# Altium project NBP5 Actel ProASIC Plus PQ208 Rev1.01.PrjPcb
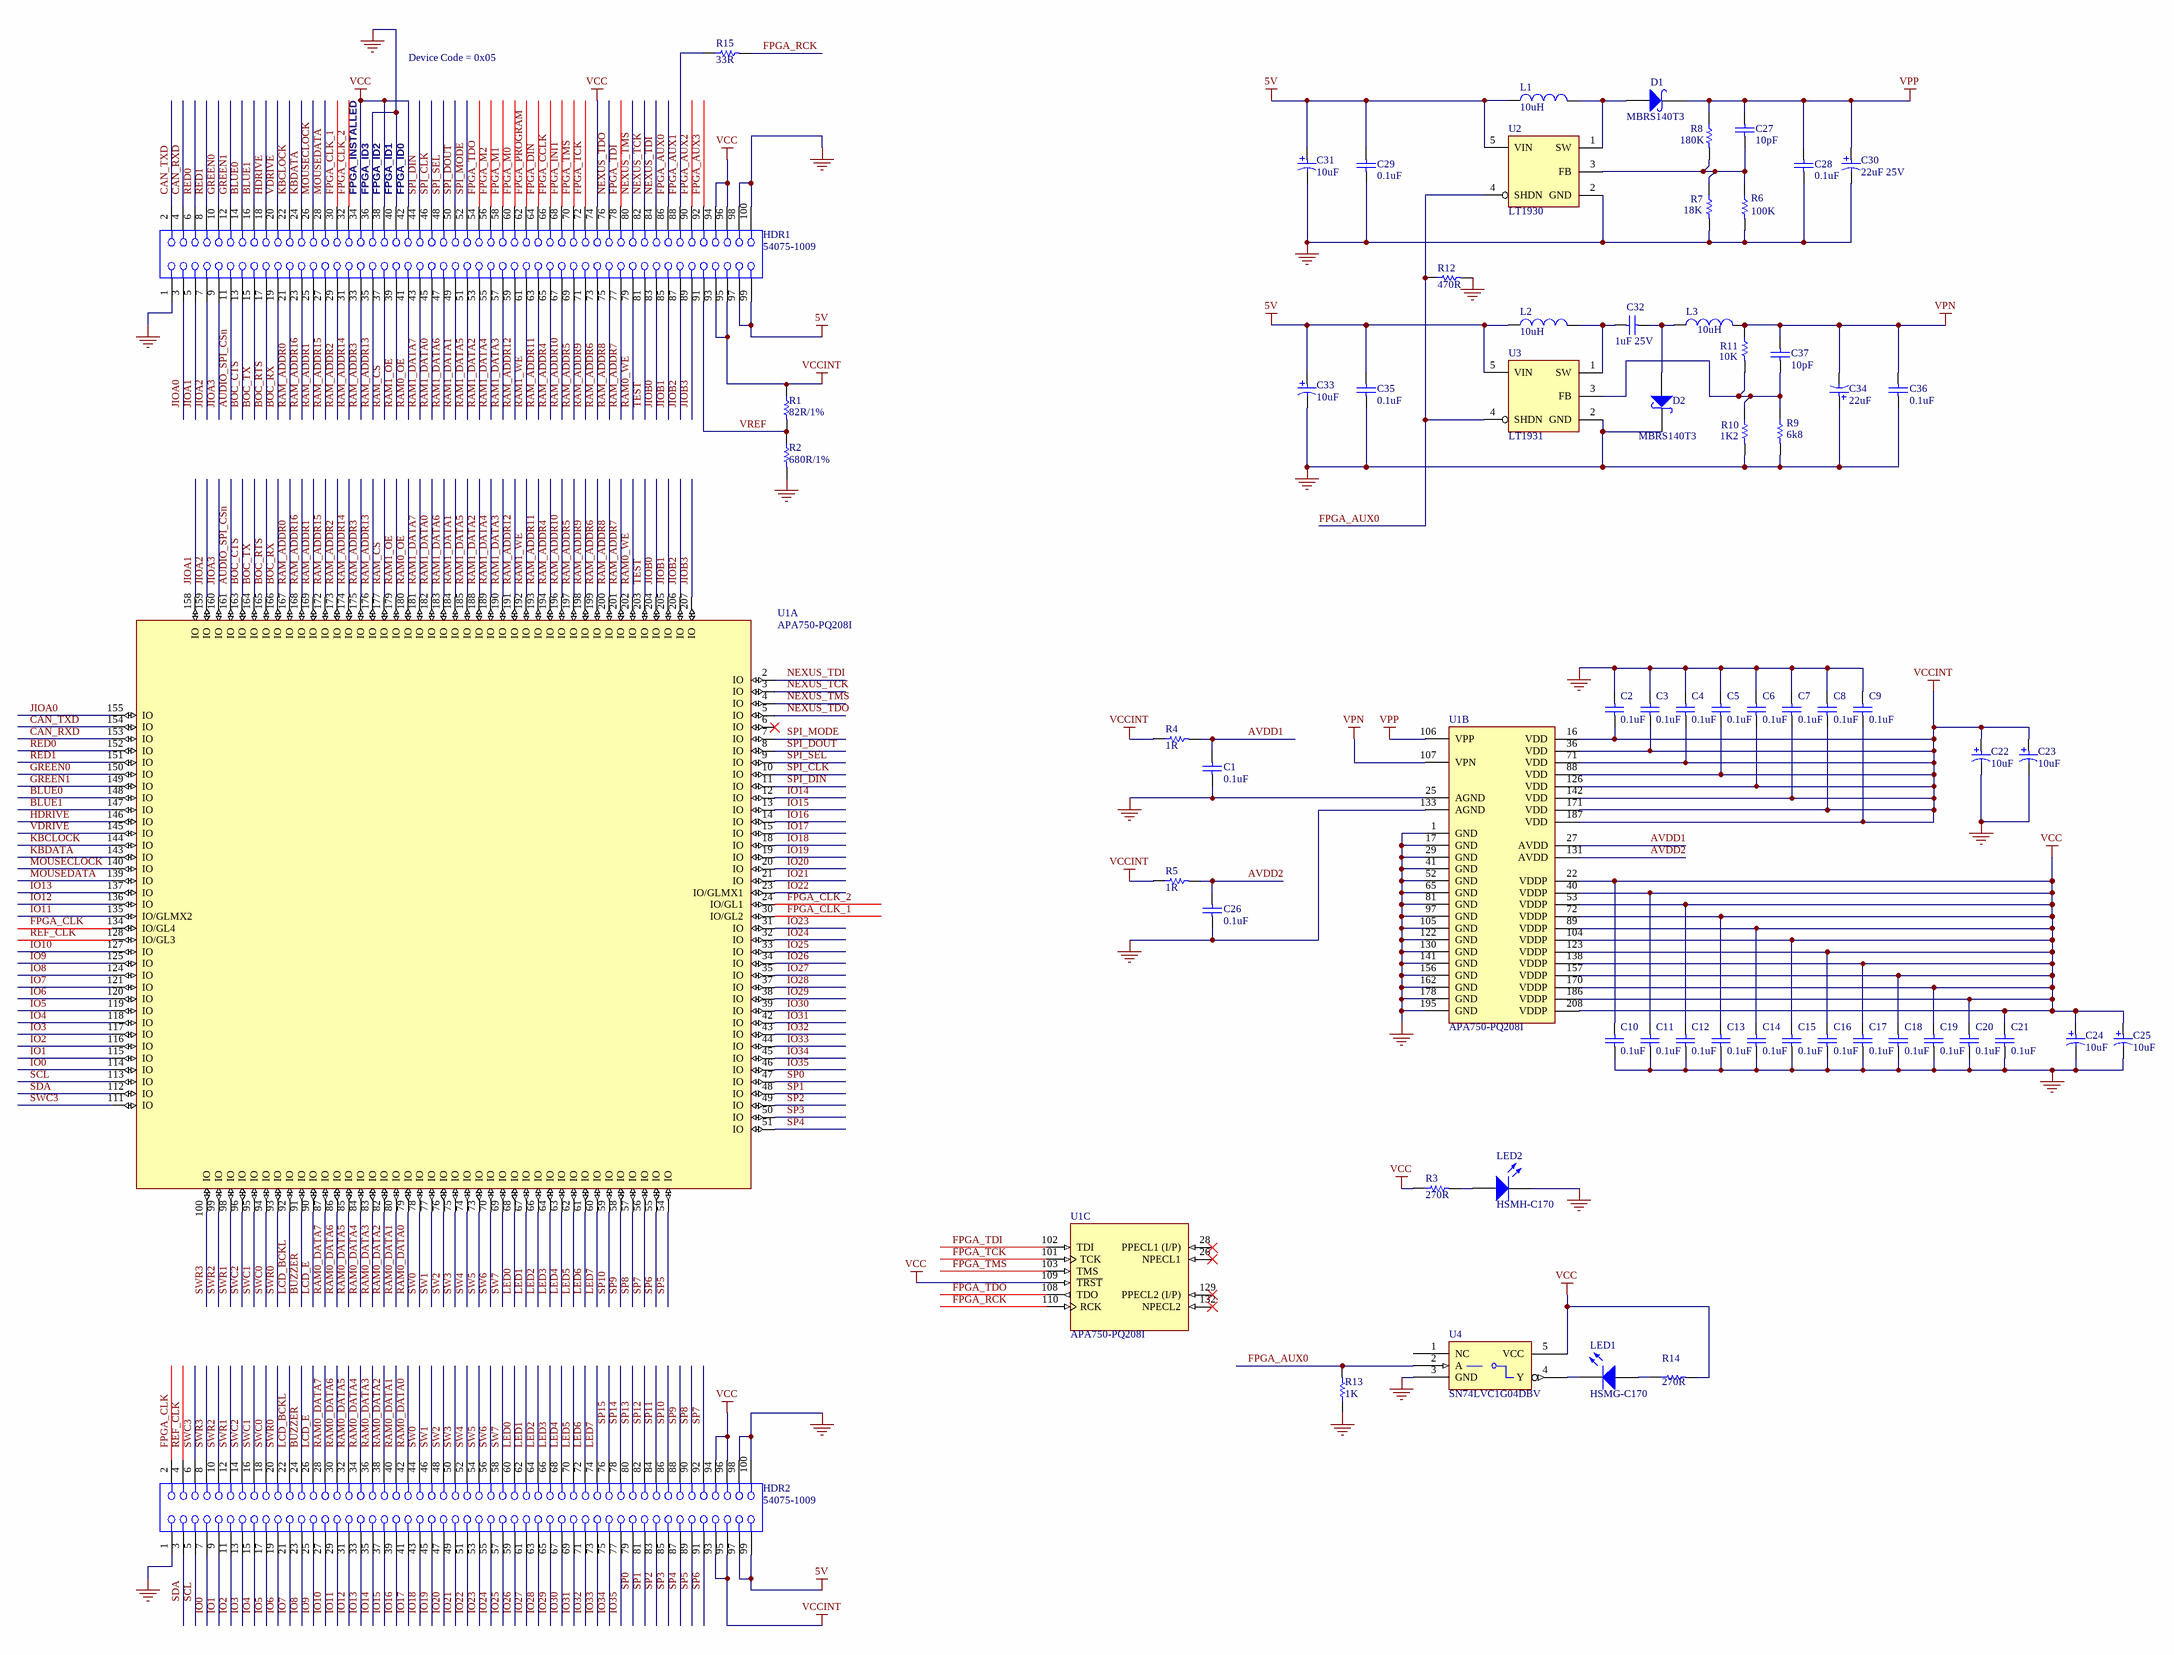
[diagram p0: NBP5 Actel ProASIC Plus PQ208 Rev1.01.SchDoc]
1 sheet, 65 parts. Net scope: global (net labels, ports and power ports of the same name join across sheets).
Board file: NBP5 Actel ProASIC Plus PQ208 Rev1.01.PcbDoc

## Sheet NBP5 Actel ProASIC Plus PQ208 Rev1.01.SchDoc: Actel APA Daughter Board
size C; Organization: Altium Limited; Address1: L3, 12a Rodborough Rd; Address2: Frenchs Forest; Address3: NSW; Address4: Australia 2086; DocumentNumber: 1; Revision: 1.01; SheetNumber: 1; SheetTotal: 1

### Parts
C1  0.1uF  [CC2012-0805]
C2  0.1uF  [CC2012-0805]
C3  0.1uF  [CC2012-0805]
C4  0.1uF  [CC2012-0805]
C5  0.1uF  [CC2012-0805]
C6  0.1uF  [CC2012-0805]
C7  0.1uF  [CC2012-0805]
C8  0.1uF  [CC2012-0805]
C9  0.1uF  [CC2012-0805]
C10  0.1uF  [CC2012-0805]
C11  0.1uF  [CC2012-0805]
C12  0.1uF  [CC2012-0805]
C13  0.1uF  [CC2012-0805]
C14  0.1uF  [CC2012-0805]
C15  0.1uF  [CC2012-0805]
C16  0.1uF  [CC2012-0805]
C17  0.1uF  [CC2012-0805]
C18  0.1uF  [CC2012-0805]
C19  0.1uF  [CC2012-0805]
C20  0.1uF  [CC2012-0805]
C21  0.1uF  [CC2012-0805]
C22  10uF  [MCCT-B]
C23  10uF  [MCCT-B]
C24  10uF  [MCCT-B]
C25  10uF  [MCCT-B]
C26  0.1uF  [CC2012-0805]
C27  10pF  [CC2012-0805]
C28  0.1uF  [CC2012-0805]
C29  0.1uF  [CC2012-0805]
C30  22uF 25V  [MCCT-D]
C31  10uF  [MCCT-B]
C32  1uF 25V  [CC3216-1206]
C33  10uF  [MCCT-B]
C34  22uF  [MCCT-D]
C35  0.1uF  [CC2012-0805]
C36  0.1uF  [CC2012-0805]
C37  10pF  [CC2012-0805]
D1  MBRS140T3  [403A]
D2  MBRS140T3  [403A]
HDR1  54075-1009  [54075]
HDR2  54075-1009  [54075]
L1  10uH  [CC4532-1812]
L2  10uH  [CC4532-1812]
L3  10uH  [CC4532-1812]
LED1  HSMG-C170  [SMD _LED]
LED2  HSMH-C170  [SMD _LED]
R1  82R/1%  [CC2012-0805]
R2  680R/1%  [CC2012-0805]
R3  270R  [CC2012-0805]
R4  1R  [CC2012-0805]
R5  1R  [CC2012-0805]
R6  100K  [CC2012-0805]
R7  18K  [CC2012-0805]
R8  180K  [CC2012-0805]
R9  6k8  [CC2012-0805]
R10  1K2  [CC2012-0805]
R11  10K  [CC2012-0805]
R12  470R  [CC2012-0805]
R13  1K  [CC2012-0805]
R14  270R  [CC2012-0805]
R15  33R  [CC2012-0805]
U1  APA750-PQ208I  [PQ208]  (parts A,B,C of 3)
U2  LT1930  [SO-G5/P.95]
U3  LT1931  [SO-G5/P.95]
U4  SN74LVC1G04DBV  [SO-G5/P.95]

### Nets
5V: C29.1 C31.1 C33.1 C35.1 HDR1.97 HDR1.99 HDR2.97 HDR2.99 L1.1 L2.1 U2.5(VIN) U3.5(VIN)
GND: C1.2 C2.1 C3.1 C4.1 C5.1 C6.1 C7.1 C8.1 C9.1 C10.2 C11.1 C12.1 C13.1 C14.1 C15.1 C16.1 C17.1 C18.1 C19.1 C20.1 C21.1 C22.2 C23.2 C24.2 C25.2 C26.2 C28.2 C29.2 C30.2 C31.2 C33.2 C34.1 C35.2 C36.2 D2.2(K) HDR1.1 HDR1.36 HDR1.40 HDR1.98 HDR1.100 HDR2.1 HDR2.98 HDR2.100 LED2.2(K) R2.2 R6.2 R7.2 R9.2 R10.2 R12.2 R13.1 U1.1(GND) U1.17(GND) U1.25(AGND) U1.29(GND) U1.41(GND) U1.52(GND) U1.65(GND) U1.81(GND) U1.97(GND) U1.105(GND) U1.122(GND) U1.130(GND) U1.133(AGND) U1.141(GND) U1.156(GND) U1.162(GND) U1.178(GND) U1.195(GND) U2.2(GND) U3.2(GND) U4.3(GND)
VCC: C10.1 C11.2 C12.2 C13.2 C14.2 C15.2 C16.2 C17.2 C18.2 C19.2 C20.2 C21.2 C24.1 C25.1 HDR1.34 HDR1.38 HDR1.42 HDR1.74 HDR1.94 HDR1.96 HDR2.94 HDR2.96 R3.1 R14.2 U1.22(VDDP) U1.40(VDDP) U1.53(VDDP) U1.72(VDDP) U1.89(VDDP) U1.104(VDDP) U1.109(~{TRST}) U1.123(VDDP) U1.138(VDDP) U1.157(VDDP) U1.170(VDDP) U1.186(VDDP) U1.208(VDDP) U4.5(VCC)
VCCINT: C2.2 C3.2 C4.2 C5.2 C6.2 C7.2 C8.2 C9.2 C22.1 C23.1 HDR1.93 HDR1.95 HDR2.93 HDR2.95 R1.1 R4.1 R5.1 U1.16(VDD) U1.36(VDD) U1.71(VDD) U1.88(VDD) U1.126(VDD) U1.142(VDD) U1.171(VDD) U1.187(VDD)
VPN: C34.2 C36.1 C37.1 L3.2 R11.1 U1.107(VPN)
VPP: C27.1 C28.1 C30.1 D1.2(K) R8.1 U1.106(VPP)
AUDIO_SPI_CSn: HDR1.11 U1.161(IO)
AVDD1: C1.1 R4.2 U1.27(AVDD)
AVDD2: C26.1 R5.2 U1.131(AVDD)
BLUE0: HDR1.14 U1.148(IO)
BLUE1: HDR1.16 U1.147(IO)
BOC_CTS: HDR1.13 U1.163(IO)
BOC_RTS: HDR1.17 U1.165(IO)
BOC_RX: HDR1.19 U1.166(IO)
BOC_TX: HDR1.15 U1.164(IO)
BUZZER: HDR2.24 U1.91(IO)
CAN_RXD: HDR1.4 U1.153(IO)
CAN_TXD: HDR1.2 U1.154(IO)
FPGA_AUX0: HDR1.86 R12.1 R13.2 U2.4(SHDN) U3.4(SHDN) U4.2(A)
FPGA_AUX1: HDR1.88 R15.1
FPGA_AUX2: HDR1.90
FPGA_AUX3: HDR1.92
FPGA_CCLK: HDR1.66
FPGA_CLK: HDR2.2 U1.134(IO/GL4)
FPGA_CLK_1: HDR1.30 U1.30(IO/GL2)
FPGA_CLK_2: HDR1.32 U1.24(IO/GL1)
FPGA_DIN: HDR1.64
FPGA_INIT: HDR1.68
FPGA_M0: HDR1.60
FPGA_M1: HDR1.58
FPGA_M2: HDR1.56
FPGA_PROGRAM: HDR1.62
FPGA_RCK: R15.2 U1.110(RCK)
FPGA_TCK: HDR1.72 U1.101(TCK)
FPGA_TDI: HDR1.78 U1.102(TDI)
FPGA_TDO: HDR1.54 U1.108(TDO)
FPGA_TMS: HDR1.70 U1.103(TMS)
GREEN0: HDR1.10 U1.150(IO)
GREEN1: HDR1.12 U1.149(IO)
HDRIVE: HDR1.18 U1.146(IO)
IO0: HDR2.7 U1.114(IO)
IO1: HDR2.9 U1.115(IO)
IO2: HDR2.11 U1.116(IO)
IO3: HDR2.13 U1.117(IO)
IO4: HDR2.15 U1.118(IO)
IO5: HDR2.17 U1.119(IO)
IO6: HDR2.19 U1.120(IO)
IO7: HDR2.21 U1.121(IO)
IO8: HDR2.23 U1.124(IO)
IO9: HDR2.25 U1.125(IO)
IO10: HDR2.27 U1.127(IO)
IO11: HDR2.29 U1.135(IO/GLMX2)
IO12: HDR2.31 U1.136(IO)
IO13: HDR2.33 U1.137(IO)
IO14: HDR2.35 U1.12(IO)
IO15: HDR2.37 U1.13(IO)
IO16: HDR2.39 U1.14(IO)
IO17: HDR2.41 U1.15(IO)
IO18: HDR2.43 U1.18(IO)
IO19: HDR2.45 U1.19(IO)
IO20: HDR2.47 U1.20(IO)
IO21: HDR2.49 U1.21(IO)
IO22: HDR2.51 U1.23(IO/GLMX1)
IO23: HDR2.53 U1.31(IO)
IO24: HDR2.55 U1.32(IO)
IO25: HDR2.57 U1.33(IO)
IO26: HDR2.59 U1.34(IO)
IO27: HDR2.61 U1.35(IO)
IO28: HDR2.63 U1.37(IO)
IO29: HDR2.65 U1.38(IO)
IO30: HDR2.67 U1.39(IO)
IO31: HDR2.69 U1.42(IO)
IO32: HDR2.71 U1.43(IO)
IO33: HDR2.73 U1.44(IO)
IO34: HDR2.75 U1.45(IO)
IO35: HDR2.77 U1.46(IO)
JIOA0: HDR1.3 U1.155(IO)
JIOA1: HDR1.5 U1.158(IO)
JIOA2: HDR1.7 U1.159(IO)
JIOA3: HDR1.9 U1.160(IO)
JIOB0: HDR1.83 U1.204(IO)
JIOB1: HDR1.85 U1.205(IO)
JIOB2: HDR1.87 U1.206(IO)
JIOB3: HDR1.89 U1.207(IO)
KBCLOCK: HDR1.22 U1.144(IO)
KBDATA: HDR1.24 U1.143(IO)
LCD_BCKL: HDR2.22 U1.92(IO)
LCD_E: HDR2.26 U1.90(IO)
LED0: HDR2.60 U1.68(IO)
LED1: HDR2.62 U1.67(IO)
LED2: HDR2.64 U1.66(IO)
LED3: HDR2.66 U1.64(IO)
LED4: HDR2.68 U1.63(IO)
LED5: HDR2.70 U1.62(IO)
LED6: HDR2.72 U1.61(IO)
LED7: HDR2.74 U1.60(IO)
MOUSECLOCK: HDR1.26 U1.140(IO)
MOUSEDATA: HDR1.28 U1.139(IO)
NEXUS_TCK: HDR1.82 U1.3(IO)
NEXUS_TDI: HDR1.84 U1.2(IO)
NEXUS_TDO: HDR1.76 U1.5(IO)
NEXUS_TMS: HDR1.80 U1.4(IO)
RAM0_DATA0: HDR2.42 U1.79(IO)
RAM0_DATA1: HDR2.40 U1.80(IO)
RAM0_DATA2: HDR2.38 U1.82(IO)
RAM0_DATA3: HDR2.36 U1.83(IO)
RAM0_DATA4: HDR2.34 U1.84(IO)
RAM0_DATA5: HDR2.32 U1.85(IO)
RAM0_DATA6: HDR2.30 U1.86(IO)
RAM0_DATA7: HDR2.28 U1.87(IO)
RAM0_OE: HDR1.41 U1.180(IO)
RAM0_WE: HDR1.79 U1.202(IO)
RAM1_DATA0: HDR1.45 U1.182(IO)
RAM1_DATA1: HDR1.49 U1.184(IO)
RAM1_DATA2: HDR1.53 U1.188(IO)
RAM1_DATA3: HDR1.57 U1.190(IO)
RAM1_DATA4: HDR1.55 U1.189(IO)
RAM1_DATA5: HDR1.51 U1.185(IO)
RAM1_DATA6: HDR1.47 U1.183(IO)
RAM1_DATA7: HDR1.43 U1.181(IO)
RAM1_OE: HDR1.39 U1.179(IO)
RAM1_WE: HDR1.61 U1.192(IO)
RAM_ADDR0: HDR1.21 U1.167(IO)
RAM_ADDR1: HDR1.25 U1.169(IO)
RAM_ADDR2: HDR1.29 U1.173(IO)
RAM_ADDR3: HDR1.33 U1.175(IO)
RAM_ADDR4: HDR1.65 U1.194(IO)
RAM_ADDR5: HDR1.69 U1.197(IO)
RAM_ADDR6: HDR1.73 U1.199(IO)
RAM_ADDR7: HDR1.77 U1.201(IO)
RAM_ADDR8: HDR1.75 U1.200(IO)
RAM_ADDR9: HDR1.71 U1.198(IO)
RAM_ADDR10: HDR1.67 U1.196(IO)
RAM_ADDR11: HDR1.63 U1.193(IO)
RAM_ADDR12: HDR1.59 U1.191(IO)
RAM_ADDR13: HDR1.35 U1.176(IO)
RAM_ADDR14: HDR1.31 U1.174(IO)
RAM_ADDR15: HDR1.27 U1.172(IO)
RAM_ADDR16: HDR1.23 U1.168(IO)
RAM_CS: HDR1.37 U1.177(IO)
RED0: HDR1.6 U1.152(IO)
RED1: HDR1.8 U1.151(IO)
REF_CLK: HDR2.4 U1.128(IO/GL3)
SCL: HDR2.5 U1.113(IO)
SDA: HDR2.3 U1.112(IO)
SP0: HDR2.79 U1.47(IO)
SP1: HDR2.81 U1.48(IO)
SP2: HDR2.83 U1.49(IO)
SP3: HDR2.85 U1.50(IO)
SP4: HDR2.87 U1.51(IO)
SP5: HDR2.89 U1.54(IO)
SP6: HDR2.91 U1.55(IO)
SP7: HDR2.92 U1.56(IO)
SP8: HDR2.90 U1.57(IO)
SP9: HDR2.88 U1.58(IO)
SP10: HDR2.86 U1.59(IO)
SP11: HDR2.84
SP12: HDR2.82
SP13: HDR2.80
SP14: HDR2.78
SP15: HDR2.76
SPI_CLK: HDR1.46 U1.10(IO)
SPI_DIN: HDR1.44 U1.11(IO)
SPI_DOUT: HDR1.50 U1.8(IO)
SPI_MODE: HDR1.52 U1.7(IO)
SPI_SEL: HDR1.48 U1.9(IO)
SW0: HDR2.44 U1.78(IO)
SW1: HDR2.46 U1.77(IO)
SW2: HDR2.48 U1.76(IO)
SW3: HDR2.50 U1.75(IO)
SW4: HDR2.52 U1.74(IO)
SW5: HDR2.54 U1.73(IO)
SW6: HDR2.56 U1.70(IO)
SW7: HDR2.58 U1.69(IO)
SWC0: HDR2.18 U1.94(IO)
SWC1: HDR2.16 U1.95(IO)
SWC2: HDR2.14 U1.96(IO)
SWC3: HDR2.6 U1.111(IO)
SWR0: HDR2.20 U1.93(IO)
SWR1: HDR2.12 U1.98(IO)
SWR2: HDR2.10 U1.99(IO)
SWR3: HDR2.8 U1.100(IO)
TEST: HDR1.81 U1.203(IO)
VDRIVE: HDR1.20 U1.145(IO)
VREF: HDR1.91 R1.2 R2.1
NetC27_2: C27.2 R6.1 R7.1 R8.2 U2.3(FB)
NetC32_1: C32.1 L2.2 U3.1(SW)
NetC32_2: C32.2 D2.1(A) L3.1
NetC37_2: C37.2 R9.1 R10.1 R11.2 U3.3(FB)
NetD1_1: D1.1(A) L1.2 U2.1(SW)
NetLED1_1: LED1.1(A) R14.1
NetLED1_2: LED1.2(K) U4.4(Y)
NetLED2_1: LED2.1(A) R3.2

Not connected (* = marked no-connect by the designer): U1 6(IO)* 26(NPECL1)* 28(PPECL1_(I/P))* 129(PPECL2_(I/P))* 132(NPECL2)*; U4 1(NC)

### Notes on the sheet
- Device Code = 0x05
- (near HDR1) FPGA_INSTALLED
- (near HDR1) FPGA_ID3
- (near HDR1) FPGA_ID2
- (near HDR1) FPGA_ID1
- (near HDR1) FPGA_ID0

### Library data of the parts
C1-C21 C26-C29 C32 C35-C37 = CAP: Capacitor
C22-C25 C30 C31 C33 C34 = CAP_POLAR: Polar Capacitor
D1 D2 = Shottky: Shottky Diode
HDR1 HDR2 = 54075-1009: Board-to-Board, Docking Station, 0.80mm (.031") Pitch, Shielded Receptacle, Vertical, Ultra Low Profile, SMT; Manufacturer: Molex; Package Information: Latest Revision: Jun-2001; Mating Height: 8.5mm; Voltage: 100V; Current: 0.5A; Contact Resistance: 40mOhm max; PCB Layout: Complies with Manufacturer's Recommendation.
L1-L3 = INDUCTOR
LED1 LED2 = HSMX-C670: Typical RED GaAs SMD LED Agilent make; Manufacturer: Generic Components; Class I: Optoelectronic; Fitted: True
R1-R15 = RES: Resistor
U1 = APA750-PQ208I: ProASICPlus APA750 Flash FPGA, 156 User IOs, 208-Pin PQFP, Speed Grade Standard, Industrial Grade; Package Information: Latest Revision: ver8.2, Jun-2003; PECL Pins: If unused, leave unconnected.; Code - JEDEC: MS-029-FA-1
U2 = LT1930: Switching Regulator; Manufacturer: Linear Technology
U3 = LT1931: Switching Regulator; Manufacturer: Linear Technology
U4 = SN74AHC1G04DBVR: Manufacturer: TI; Fitted: True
